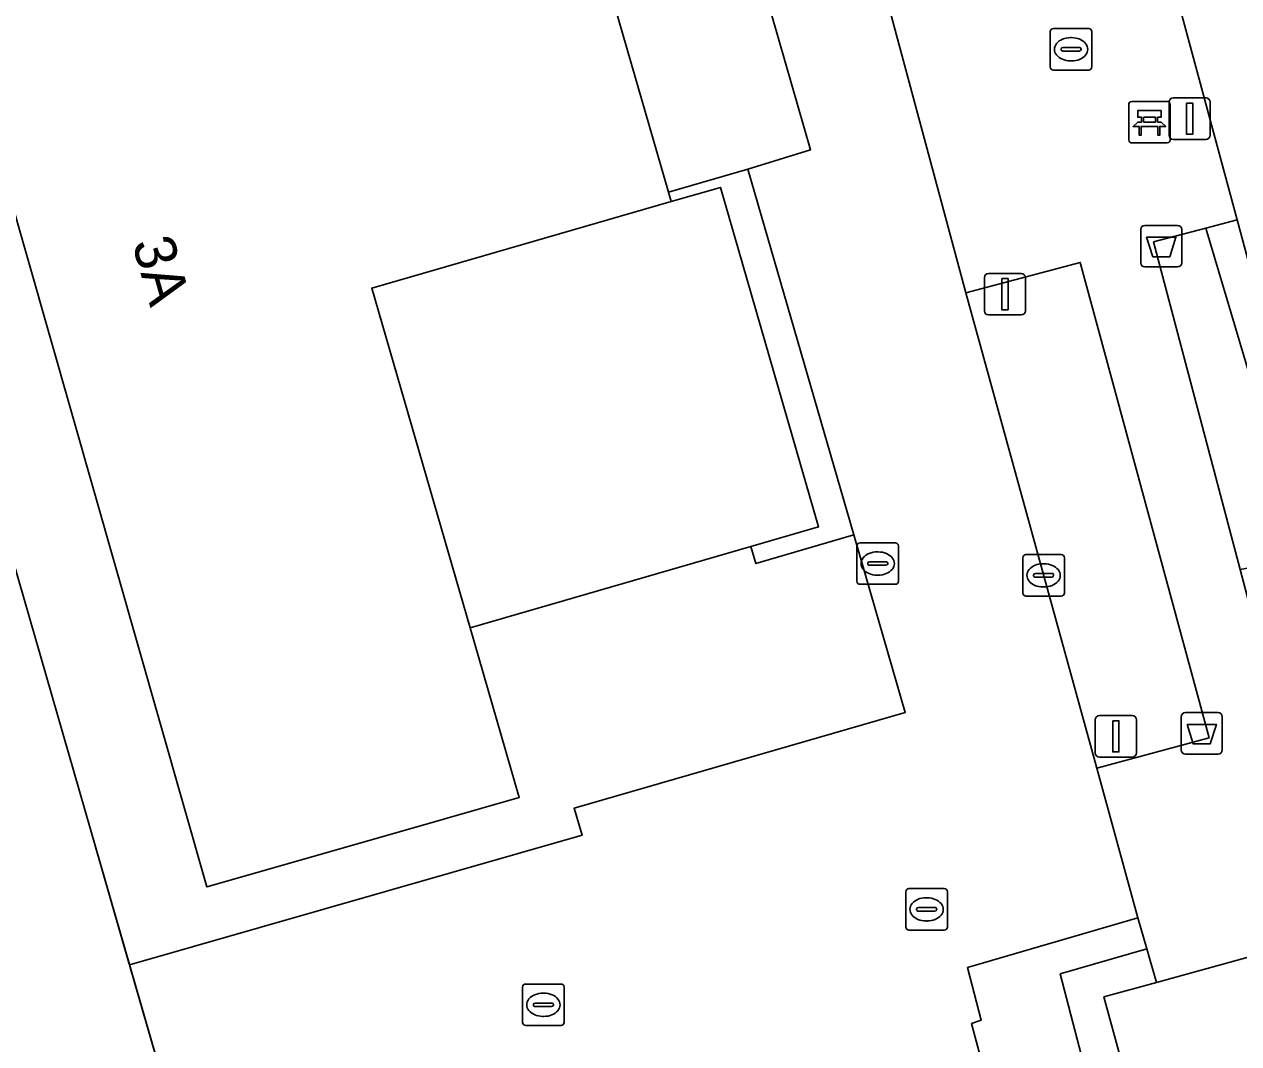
# Model space of a CAD drawing. Extents: x 159053 to 160042, y 380449 to 381423.
# Drawn here: x 159355.9 to 159385.17, y 380559.07 to 380583.63 of the extents above; entities that cross this region are included whole.
import ezdxf

# ---------------------------------------------------------------- set-up
doc = ezdxf.new("R2010")
doc.units = 0
for name, color, linetype in [('IMGEO_Afvalbak', 7, 'Continuous'), ('IMGEO_Bank', 7, 'Continuous'), ('IMGEO_Brandkraan', 7, 'Continuous'), ('IMGEO_Groenvoorziening', 7, 'Continuous'), ('IMGEO_Haag', 7, 'Continuous'), ('IMGEO_Hek', 7, 'Continuous'), ('IMGEO_Kolk', 7, 'Continuous'), ('IMGEO_Lichtmast', 7, 'Continuous'), ('IMGEO_Pand', 7, 'Continuous'), ('IMGEO_Pand_nummerreeks', 7, 'Continuous'), ('IMGEO_Rioolput', 7, 'Continuous'), ('IMGEO_Terreindeel_gesloten', 7, 'Continuous'), ('IMGEO_Terreindeel_halfverhard', 7, 'Continuous'), ('IMGEO_Voetpad_open', 7, 'Continuous')]:
    doc.layers.add(name, color=color, linetype=linetype)

msp = doc.modelspace()

# ---------------------------------------------------------------- linework, layer by layer
at = {"layer": 'IMGEO_Afvalbak'}
for p, q in [((159382.904, 380578.789), (159383.694, 380578.789)), ((159383.694, 380578.789), (159382.904, 380578.789)), ((159382.804, 380577.889), (159382.804, 380578.689)), ((159382.804, 380578.689), (159382.804, 380577.889)), ((159383.794, 380578.689), (159383.794, 380577.889)), ((159383.794, 380577.889), (159383.794, 380578.689)), ((159383.694, 380577.789), (159382.904, 380577.789)), ((159382.904, 380577.789), (159383.694, 380577.789)), ((159383.779, 380566.15), (159383.779, 380566.95)), ((159383.779, 380566.95), (159383.779, 380566.15)), ((159383.879, 380567.05), (159384.669, 380567.05)), ((159384.669, 380567.05), (159383.879, 380567.05)), ((159384.769, 380566.95), (159384.769, 380566.15)), ((159384.769, 380566.15), (159384.769, 380566.95)), ((159384.669, 380566.05), (159383.879, 380566.05)), ((159383.879, 380566.05), (159384.669, 380566.05))]:
    msp.add_line(p, q, dxfattribs=at)
for points in [[(159382.947, 380578.503), (159383.651, 380578.503), (159383.502, 380578.033), (159383.096, 380578.033), (159382.947, 380578.503)], [(159383.922, 380566.764), (159384.626, 380566.764), (159384.477, 380566.294), (159384.071, 380566.294), (159383.922, 380566.764)]]:
    msp.add_lwpolyline(points, dxfattribs=at)
for centre, start, end in [((159382.904, 380578.689), 90, 180), ((159382.904, 380578.689), 90, 180), ((159383.694, 380578.689), 0, 90), ((159383.694, 380578.689), 360, 90), ((159382.904, 380577.889), 180, 270), ((159382.904, 380577.889), 180, 270), ((159383.694, 380577.889), 270, 0), ((159383.694, 380577.889), 270, 0), ((159383.879, 380566.95), 90, 180), ((159383.879, 380566.95), 90, 180), ((159384.669, 380566.95), 0, 90), ((159384.669, 380566.95), 360, 90), ((159383.879, 380566.15), 180, 270), ((159383.879, 380566.15), 180, 270), ((159384.669, 380566.15), 270, 0), ((159384.669, 380566.15), 270, 0)]:
    msp.add_arc(centre, 0.1, start, end, dxfattribs=at)
at = {"layer": 'IMGEO_Bank'}
for p, q in [((159382.591, 380581.778), (159383.432, 380581.778)), ((159383.432, 380581.778), (159382.591, 380581.778)), ((159383.516, 380581.703), (159383.516, 380580.862)), ((159383.516, 380580.862), (159383.516, 380581.703)), ((159382.516, 380580.853), (159382.516, 380581.694)), ((159382.516, 380581.694), (159382.516, 380580.853)), ((159383.213, 380581.176), (159382.82, 380581.176)), ((159382.825, 380581.284), (159382.825, 380581.39)), ((159382.869, 380581.39), (159382.869, 380581.284)), ((159383.157, 380581.396), (159382.875, 380581.396)), ((159382.875, 380581.278), (159383.157, 380581.278)), ((159383.163, 380581.284), (159383.163, 380581.39)), ((159383.207, 380581.39), (159383.207, 380581.284)), ((159383.441, 380580.778), (159382.6, 380580.778)), ((159382.6, 380580.778), (159383.441, 380580.778))]:
    msp.add_line(p, q, dxfattribs=at)
for points in [[(159382.819, 380581.396), (159382.733, 380581.396), (159382.733, 380581.557), (159383.296, 380581.557), (159383.296, 380581.396), (159383.213, 380581.396)], [(159382.763, 380581.176), (159382.621, 380581.176), (159382.733, 380581.278), (159382.819, 380581.278)], [(159382.813, 380581.169), (159382.813, 380580.962), (159382.77, 380580.962), (159382.77, 380581.169)], [(159383.213, 380581.278), (159383.296, 380581.278), (159383.408, 380581.176), (159383.269, 380581.176)], [(159383.263, 380581.169), (159383.263, 380580.962), (159383.219, 380580.962), (159383.219, 380581.169)]]:
    msp.add_lwpolyline(points, dxfattribs=at)
for centre, radius, start, end in [((159382.594, 380581.7), 0.0779, 92.4484, 184.2845), ((159382.594, 380581.7), 0.0779, 92.4484, 184.2845), ((159383.438, 380581.7), 0.0779, 2.4484, 94.2845), ((159383.438, 380581.7), 0.0779, 2.4484, 94.2845), ((159382.763, 380581.169), 0.00671, 2.8957, 87.1043), ((159382.82, 380581.169), 0.00671, 92.8957, 177.1043), ((159382.818, 380581.389), 0.00671, 2.8957, 87.1043), ((159382.818, 380581.285), 0.00671, 272.8957, 357.1043), ((159382.875, 380581.389), 0.00671, 92.8957, 177.1043), ((159382.875, 380581.285), 0.00671, 182.8957, 267.1043), ((159383.157, 380581.389), 0.00671, 2.8957, 87.1043), ((159383.157, 380581.285), 0.00671, 272.8957, 357.1043), ((159383.214, 380581.389), 0.00671, 92.8957, 177.1043), ((159383.214, 380581.285), 0.00671, 182.8957, 267.1043), ((159383.212, 380581.169), 0.00671, 2.8957, 87.1043), ((159383.269, 380581.169), 0.00671, 92.8957, 177.1043), ((159382.594, 380580.856), 0.0779, 182.4484, 274.2845), ((159382.594, 380580.856), 0.0779, 182.4484, 274.2845), ((159383.438, 380580.856), 0.0779, 272.4484, 4.2845), ((159383.438, 380580.856), 0.0779, 272.4484, 4.2845)]:
    msp.add_arc(centre, radius, start, end, dxfattribs=at)
at = {"layer": 'IMGEO_Brandkraan'}
for p, q in [((159375.966, 380570.216), (159375.966, 380571.068)), ((159376.041, 380571.142), (159376.893, 380571.142)), ((159376.454, 380570.922), (159376.479, 380570.922)), ((159376.967, 380571.068), (159376.967, 380570.216)), ((159376.225, 380570.636), (159376.225, 380570.648)), ((159376.663, 380570.599), (159376.265, 380570.599)), ((159376.268, 380570.685), (159376.666, 380570.685)), ((159376.709, 380570.648), (159376.709, 380570.636)), ((159376.477, 380570.362), (159376.452, 380570.362)), ((159376.893, 380570.142), (159376.041, 380570.142))]:
    msp.add_line(p, q, dxfattribs=at)
for points in [[(159375.966, 380570.216), (159375.966, 380571.068)], [(159376.041, 380571.142), (159376.893, 380571.142)], [(159376.967, 380571.068), (159376.967, 380570.216)], [(159376.893, 380570.142), (159376.041, 380570.142)]]:
    msp.add_lwpolyline(points, dxfattribs=at)
for centre, radius, start, end in [((159376.043, 380571.066), 0.0765, 91.552, 178.448), ((159376.043, 380571.066), 0.0765, 91.552, 178.448), ((159376.891, 380571.066), 0.0765, 1.552, 88.448), ((159376.891, 380571.066), 0.0765, 1.552, 88.448), ((159376.265, 380570.645), 0.0403, 85.8775, 175.7526), ((159376.262, 380570.635), 0.0366, 178.938, 274.7102), ((159376.666, 380570.642), 0.043, 264.8664, 352.4533), ((159376.67, 380570.647), 0.0386, 1.7309, 96.639), ((159376.043, 380570.218), 0.0765, 181.552, 268.448), ((159376.043, 380570.218), 0.0765, 181.552, 268.448), ((159376.891, 380570.218), 0.0765, 271.552, 358.448), ((159376.891, 380570.218), 0.0765, 271.552, 358.448)]:
    msp.add_arc(centre, radius, start, end, dxfattribs=at)
for centre, major_axis, ratio, start_param, end_param in [((159376.453, 380570.642), (-0.387, 0.002), 0.722429, 4.712389, 7.853982), ((159376.478, 380570.642), (-0.39, 0.002), 0.717154, 1.570796, 4.712389)]:
    msp.add_ellipse(centre, major_axis=major_axis, ratio=ratio, start_param=start_param, end_param=end_param, dxfattribs=at)
at = {"layer": 'IMGEO_Groenvoorziening'}
for points in [[(159357.369, 380564.683), (159349.331, 380592.56), (159346.947, 380600.826), (159346.774, 380601.426), (159338.841, 380599.209), (159338.36, 380599.075), (159339.254, 380595.623), (159344.292, 380576.221), (159349.404, 380556.748), (159351.079, 380550.293), (159360.774, 380552.877), (159358.448, 380560.94), (159358.439, 380560.973), (159358.424, 380561.023)], [(159422.093, 380552.135), (159386.743, 380542.548), (159381.917, 380560.199), (159383.181, 380560.548), (159382.949, 380561.361), (159380.865, 380560.752), (159385.994, 380541.036), (159423.423, 380551.328), (159421.053, 380559.766), (159454.836, 380569.06), (159456.103, 380570.642), (159451.468, 380587.596), (159461.029, 380590.266), (159460.552, 380592.05), (159460.061, 380591.918), (159460.426, 380590.563), (159450.507, 380587.804), (159455.23, 380570.048), (159419.835, 380560.5)], [(159385.129, 380578.922), (159384.374, 380578.723), (159386.292, 380572.275), (159386.633, 380571.661), (159387.086, 380571.784), (159386.902, 380572.418), (159386.729, 380572.996)], [(159386.633, 380571.661), (159386.292, 380572.275), (159384.374, 380578.723), (159383.114, 380578.39), (159385.201, 380570.495), (159386.808, 380570.803)], [(159384.456, 380566.438), (159381.347, 380577.898), (159378.59, 380577.165), (159381.743, 380565.708)]]:
    msp.add_lwpolyline(points, close=True, dxfattribs=at)
msp.add_lwpolyline([(159478.465, 380596.984), (159460.973, 380592.164), (159460.552, 380592.05), (159461.029, 380590.266), (159451.468, 380587.596), (159456.103, 380570.642), (159454.836, 380569.06), (159421.053, 380559.766), (159423.423, 380551.328), (159385.994, 380541.036), (159380.865, 380560.752), (159382.949, 380561.361), (159382.736, 380562.106), (159378.627, 380560.909), (159378.96, 380559.642), (159378.727, 380559.561), (159384.113, 380539.402), (159366.014, 380534.705), (159367.048, 380531.119), (159403.642, 380540.747), (159438.635, 380550.23), (159479.833, 380596.64)], dxfattribs=at)
at = {"layer": 'IMGEO_Haag'}
msp.add_lwpolyline([(159422.093, 380552.135), (159386.743, 380542.548), (159381.917, 380560.199), (159383.181, 380560.548), (159382.949, 380561.361), (159380.865, 380560.752), (159385.994, 380541.036), (159423.423, 380551.328), (159421.053, 380559.766), (159454.836, 380569.06), (159456.103, 380570.642), (159451.468, 380587.596), (159461.029, 380590.266), (159460.552, 380592.05), (159460.061, 380591.918), (159460.426, 380590.563), (159450.507, 380587.804), (159455.23, 380570.048), (159419.835, 380560.5)], close=True, dxfattribs=at)
at = {"layer": 'IMGEO_Hek'}
for points in [[(159378.936, 380601.858), (159385.129, 380578.922)], [(159357.369, 380564.683), (159349.331, 380592.56)], [(159385.129, 380578.922), (159386.729, 380572.996), (159386.902, 380572.418), (159413.391, 380579.576), (159420.037, 380581.372), (159419.844, 380582.068)], [(159366.014, 380534.705), (159360.774, 380552.877), (159357.369, 380564.683)], [(159389.787, 380562.37), (159383.181, 380560.548)], [(159383.181, 380560.548), (159381.917, 380560.199), (159386.743, 380542.548), (159422.093, 380552.135), (159419.835, 380560.5)]]:
    msp.add_lwpolyline(points, dxfattribs=at)
at = {"layer": 'IMGEO_Kolk'}
for p, q in [((159380.625, 380582.607), (159380.625, 380583.459)), ((159380.7, 380583.533), (159381.552, 380583.533)), ((159381.626, 380583.459), (159381.626, 380582.607)), ((159381.113, 380583.313), (159381.138, 380583.313)), ((159380.884, 380583.027), (159380.884, 380583.039)), ((159381.322, 380582.99), (159380.924, 380582.99)), ((159380.927, 380583.076), (159381.325, 380583.076)), ((159381.368, 380583.039), (159381.368, 380583.027)), ((159381.136, 380582.753), (159381.111, 380582.753)), ((159381.552, 380582.533), (159380.7, 380582.533)), ((159379.963, 380569.93), (159379.963, 380570.782)), ((159380.038, 380570.856), (159380.89, 380570.856)), ((159380.451, 380570.636), (159380.476, 380570.636)), ((159380.964, 380570.782), (159380.964, 380569.93)), ((159380.222, 380570.35), (159380.222, 380570.362)), ((159380.66, 380570.313), (159380.262, 380570.313)), ((159380.265, 380570.399), (159380.663, 380570.399)), ((159380.706, 380570.362), (159380.706, 380570.35)), ((159380.474, 380570.076), (159380.449, 380570.076)), ((159380.89, 380569.856), (159380.038, 380569.856)), ((159367.91, 380559.583), (159367.91, 380560.435)), ((159367.985, 380560.509), (159368.837, 380560.509)), ((159368.911, 380560.435), (159368.911, 380559.583)), ((159368.212, 380560.052), (159368.61, 380560.052)), ((159368.398, 380560.289), (159368.423, 380560.289)), ((159368.169, 380560.003), (159368.169, 380560.015)), ((159368.607, 380559.966), (159368.209, 380559.966)), ((159368.653, 380560.015), (159368.653, 380560.003)), ((159368.837, 380559.509), (159367.985, 380559.509)), ((159368.421, 380559.729), (159368.396, 380559.729))]:
    msp.add_line(p, q, dxfattribs=at)
for points in [[(159380.625, 380582.607), (159380.625, 380583.459)], [(159380.7, 380583.533), (159381.552, 380583.533)], [(159381.626, 380583.459), (159381.626, 380582.607)], [(159381.552, 380582.533), (159380.7, 380582.533)], [(159379.963, 380569.93), (159379.963, 380570.782)], [(159380.038, 380570.856), (159380.89, 380570.856)], [(159380.964, 380570.782), (159380.964, 380569.93)], [(159380.89, 380569.856), (159380.038, 380569.856)], [(159367.91, 380559.583), (159367.91, 380560.435)], [(159367.985, 380560.509), (159368.837, 380560.509)], [(159368.911, 380560.435), (159368.911, 380559.583)], [(159368.837, 380559.509), (159367.985, 380559.509)]]:
    msp.add_lwpolyline(points, dxfattribs=at)
for centre, radius, start, end in [((159380.702, 380583.457), 0.0765, 91.552, 178.448), ((159380.702, 380583.457), 0.0765, 91.552, 178.448), ((159381.55, 380583.457), 0.0765, 1.552, 88.448), ((159381.55, 380583.457), 0.0765, 1.552, 88.448), ((159380.924, 380583.036), 0.0403, 85.8775, 175.7526), ((159380.921, 380583.026), 0.0366, 178.938, 274.7102), ((159381.325, 380583.033), 0.043, 264.8664, 352.4533), ((159381.329, 380583.038), 0.0386, 1.7309, 96.639), ((159380.702, 380582.609), 0.0765, 181.552, 268.448), ((159380.702, 380582.609), 0.0765, 181.552, 268.448), ((159381.55, 380582.609), 0.0765, 271.552, 358.448), ((159381.55, 380582.609), 0.0765, 271.552, 358.448), ((159380.04, 380570.78), 0.0765, 91.552, 178.448), ((159380.04, 380570.78), 0.0765, 91.552, 178.448), ((159380.888, 380570.78), 0.0765, 1.552, 88.448), ((159380.888, 380570.78), 0.0765, 1.552, 88.448), ((159380.262, 380570.359), 0.0403, 85.8775, 175.7526), ((159380.259, 380570.349), 0.0366, 178.938, 274.7102), ((159380.663, 380570.356), 0.043, 264.8664, 352.4533), ((159380.667, 380570.361), 0.0386, 1.7309, 96.639), ((159380.04, 380569.932), 0.0765, 181.552, 268.448), ((159380.04, 380569.932), 0.0765, 181.552, 268.448), ((159380.888, 380569.932), 0.0765, 271.552, 358.448), ((159380.888, 380569.932), 0.0765, 271.552, 358.448), ((159367.987, 380560.433), 0.0765, 91.552, 178.448), ((159367.987, 380560.433), 0.0765, 91.552, 178.448), ((159368.835, 380560.433), 0.0765, 1.552, 88.448), ((159368.835, 380560.433), 0.0765, 1.552, 88.448), ((159368.209, 380560.012), 0.0403, 85.8775, 175.7526), ((159368.614, 380560.014), 0.0386, 1.7309, 96.639), ((159368.206, 380560.002), 0.0366, 178.938, 274.7102), ((159368.61, 380560.009), 0.043, 264.8664, 352.4533), ((159367.987, 380559.585), 0.0765, 181.552, 268.448), ((159367.987, 380559.585), 0.0765, 181.552, 268.448), ((159368.835, 380559.585), 0.0765, 271.552, 358.448), ((159368.835, 380559.585), 0.0765, 271.552, 358.448)]:
    msp.add_arc(centre, radius, start, end, dxfattribs=at)
for centre, major_axis, ratio, start_param, end_param in [((159381.112, 380583.033), (-0.387, 0.002), 0.722429, 4.712389, 7.853982), ((159381.137, 380583.033), (-0.39, 0.002), 0.717154, 1.570796, 4.712389), ((159380.45, 380570.356), (-0.387, 0.002), 0.722429, 4.712389, 7.853982), ((159380.475, 380570.356), (-0.39, 0.002), 0.717154, 1.570796, 4.712389), ((159368.397, 380560.009), (-0.387, 0.002), 0.722429, 4.712389, 7.853982), ((159368.422, 380560.009), (-0.39, 0.002), 0.717154, 1.570796, 4.712389)]:
    msp.add_ellipse(centre, major_axis=major_axis, ratio=ratio, start_param=start_param, end_param=end_param, dxfattribs=at)
at = {"layer": 'IMGEO_Lichtmast'}
for p, q in [((159383.487, 380580.962), (159383.487, 380581.762)), ((159383.487, 380581.762), (159383.487, 380580.962)), ((159383.587, 380581.862), (159384.377, 380581.862)), ((159384.377, 380581.862), (159383.587, 380581.862)), ((159384.477, 380581.762), (159384.477, 380580.962)), ((159384.477, 380580.962), (159384.477, 380581.762)), ((159384.377, 380580.862), (159383.587, 380580.862)), ((159383.587, 380580.862), (159384.377, 380580.862)), ((159379.136, 380577.631), (159379.926, 380577.631)), ((159379.926, 380577.631), (159379.136, 380577.631)), ((159379.036, 380576.731), (159379.036, 380577.531)), ((159379.036, 380577.531), (159379.036, 380576.731)), ((159380.026, 380577.531), (159380.026, 380576.731)), ((159380.026, 380576.731), (159380.026, 380577.531)), ((159379.926, 380576.631), (159379.136, 380576.631)), ((159379.136, 380576.631), (159379.926, 380576.631)), ((159381.71, 380566.078), (159381.71, 380566.878)), ((159381.71, 380566.878), (159381.71, 380566.078)), ((159381.81, 380566.978), (159382.6, 380566.978)), ((159382.6, 380566.978), (159381.81, 380566.978)), ((159382.7, 380566.878), (159382.7, 380566.078)), ((159382.7, 380566.078), (159382.7, 380566.878)), ((159382.6, 380565.978), (159381.81, 380565.978)), ((159381.81, 380565.978), (159382.6, 380565.978))]:
    msp.add_line(p, q, dxfattribs=at)
for points in [[(159383.907, 380581.737), (159384.057, 380581.737), (159384.057, 380580.987), (159383.907, 380580.987), (159383.907, 380581.737)], [(159379.456, 380577.506), (159379.606, 380577.506), (159379.606, 380576.756), (159379.456, 380576.756), (159379.456, 380577.506)], [(159382.13, 380566.853), (159382.28, 380566.853), (159382.28, 380566.103), (159382.13, 380566.103), (159382.13, 380566.853)]]:
    msp.add_lwpolyline(points, dxfattribs=at)
for centre, start, end in [((159383.587, 380581.762), 90, 180), ((159383.587, 380581.762), 90, 180), ((159384.377, 380581.762), 0, 90), ((159384.377, 380581.762), 360, 90), ((159383.587, 380580.962), 180, 270), ((159383.587, 380580.962), 180, 270), ((159384.377, 380580.962), 270, 0), ((159384.377, 380580.962), 270, 0), ((159379.136, 380577.531), 90, 180), ((159379.136, 380577.531), 90, 180), ((159379.926, 380577.531), 0, 90), ((159379.926, 380577.531), 360, 90), ((159379.136, 380576.731), 180, 270), ((159379.136, 380576.731), 180, 270), ((159379.926, 380576.731), 270, 0), ((159379.926, 380576.731), 270, 0), ((159381.81, 380566.878), 90, 180), ((159381.81, 380566.878), 90, 180), ((159382.6, 380566.878), 0, 90), ((159382.6, 380566.878), 360, 90), ((159381.81, 380566.078), 180, 270), ((159381.81, 380566.078), 180, 270), ((159382.6, 380566.078), 270, 0), ((159382.6, 380566.078), 270, 0)]:
    msp.add_arc(centre, 0.1, start, end, dxfattribs=at)
at = {"layer": 'IMGEO_Pand'}
msp.add_lwpolyline([(159366.079, 380594.878), (159362.454, 380593.844), (159361.878, 380595.864), (159359.474, 380595.178), (159360.05, 380593.158), (159352.285, 380590.943), (159359.174, 380566.798), (159360.3, 380562.854), (159365.109, 380564.227), (159367.83, 380565.003), (159366.645, 380569.096), (159364.276, 380577.279), (159371.491, 380579.362), (159371.423, 380579.593), (159368.96, 380588.123), (159368.078, 380587.872)], close=True, dxfattribs=at)
at = {"layer": 'IMGEO_Rioolput'}
for p, q in [((159377.144, 380561.882), (159377.144, 380562.734)), ((159377.219, 380562.808), (159378.071, 380562.808)), ((159378.145, 380562.734), (159378.145, 380561.882)), ((159377.632, 380562.588), (159377.657, 380562.588)), ((159377.403, 380562.302), (159377.403, 380562.314)), ((159377.841, 380562.265), (159377.443, 380562.265)), ((159377.446, 380562.351), (159377.844, 380562.351)), ((159377.887, 380562.314), (159377.887, 380562.302)), ((159378.071, 380561.808), (159377.219, 380561.808)), ((159377.655, 380562.028), (159377.63, 380562.028))]:
    msp.add_line(p, q, dxfattribs=at)
for points in [[(159377.144, 380561.882), (159377.144, 380562.734)], [(159377.219, 380562.808), (159378.071, 380562.808)], [(159378.145, 380562.734), (159378.145, 380561.882)], [(159378.071, 380561.808), (159377.219, 380561.808)]]:
    msp.add_lwpolyline(points, dxfattribs=at)
for centre, radius, start, end in [((159377.221, 380562.732), 0.0765, 91.552, 178.448), ((159377.221, 380562.732), 0.0765, 91.552, 178.448), ((159378.069, 380562.732), 0.0765, 1.552, 88.448), ((159378.069, 380562.732), 0.0765, 1.552, 88.448), ((159377.443, 380562.311), 0.0403, 85.8775, 175.7526), ((159377.44, 380562.301), 0.0366, 178.938, 274.7102), ((159377.844, 380562.308), 0.043, 264.8664, 352.4533), ((159377.848, 380562.313), 0.0386, 1.7309, 96.639), ((159377.221, 380561.884), 0.0765, 181.552, 268.448), ((159377.221, 380561.884), 0.0765, 181.552, 268.448), ((159378.069, 380561.884), 0.0765, 271.552, 358.448), ((159378.069, 380561.884), 0.0765, 271.552, 358.448)]:
    msp.add_arc(centre, radius, start, end, dxfattribs=at)
for centre, major_axis, ratio, start_param, end_param in [((159377.631, 380562.308), (-0.387, 0.002), 0.722429, 4.712389, 7.853982), ((159377.656, 380562.308), (-0.39, 0.002), 0.717154, 1.570796, 4.712389)]:
    msp.add_ellipse(centre, major_axis=major_axis, ratio=ratio, start_param=start_param, end_param=end_param, dxfattribs=at)
at = {"layer": 'IMGEO_Terreindeel_gesloten'}
msp.add_lwpolyline([(159419.835, 380560.5), (159417.331, 380569.97), (159409.569, 380567.829), (159389.787, 380562.37), (159383.181, 380560.548), (159381.917, 380560.199), (159386.743, 380542.548), (159422.093, 380552.135)], close=True, dxfattribs=at)
at = {"layer": 'IMGEO_Terreindeel_halfverhard'}
msp.add_lwpolyline([(159411.978, 380611.14), (159410.439, 380616.826), (159377.318, 380607.849), (159377.482, 380607.241), (159378.936, 380601.858), (159385.129, 380578.922), (159386.729, 380572.996), (159386.902, 380572.418), (159413.415, 380579.583), (159420.037, 380581.372), (159419.844, 380582.068), (159418.261, 380587.917)], close=True, dxfattribs=at)
at = {"layer": 'IMGEO_Voetpad_open'}
for points in [[(159378.727, 380559.561), (159378.96, 380559.642), (159378.627, 380560.909), (159382.736, 380562.106), (159381.743, 380565.708), (159378.59, 380577.165), (159372.458, 380599.947), (159370.43, 380607.703), (159370.122, 380608.884), (159369.608, 380608.744), (159368.494, 380612.849), (159351.357, 380608.203), (159350.078, 380607.857), (159348.899, 380607.537), (159349.047, 380607.148), (159347.263, 380606.676), (159345.349, 380606.17), (159346.774, 380601.426), (159346.947, 380600.826), (159349.47, 380601.52), (159364.058, 380605.534)], [(159373.131, 380608.456), (159375.231, 380600.697), (159372.458, 380599.947), (159378.59, 380577.165), (159381.347, 380577.898), (159384.456, 380566.438), (159381.743, 380565.708), (159382.736, 380562.106), (159382.949, 380561.361), (159383.181, 380560.548), (159389.787, 380562.37), (159409.569, 380567.829), (159417.331, 380569.97), (159416.517, 380573.072), (159415.161, 380578.241), (159450.507, 380587.804), (159460.426, 380590.563), (159460.061, 380591.918), (159458.856, 380591.727), (159425.519, 380582.771), (159425.367, 380583.331), (159423.745, 380589.306), (159417.429, 380612.57)], [(159411.978, 380611.14), (159418.261, 380587.917), (159419.844, 380582.068), (159420.037, 380581.372), (159413.415, 380579.583), (159414.705, 380574.74), (159386.151, 380566.901), (159385.201, 380570.495), (159383.114, 380578.39), (159384.374, 380578.723), (159385.129, 380578.922), (159378.936, 380601.858), (159378.191, 380601.66), (159376.974, 380601.336), (159375.567, 380606.708), (159375.484, 380607.024), (159374.673, 380610.12)], [(159364.058, 380605.534), (159349.47, 380601.52), (159346.947, 380600.826), (159349.331, 380592.56), (159357.369, 380564.683), (159358.424, 380561.023), (159358.439, 380560.973), (159369.343, 380564.094), (159369.154, 380564.747), (159377.128, 380567.056), (159376.291, 380569.946)], [(159366.712, 380604.359), (159366.995, 380603.315), (159368.482, 380597.841), (159369.159, 380595.348), (159368.873, 380595.27), (159370.801, 380588.679), (159372.405, 380589.101), (159374.85, 380580.61), (159373.337, 380580.146), (159375.89, 380571.329), (159376.291, 380569.946), (159377.128, 380567.056), (159369.154, 380564.747), (159369.343, 380564.094), (159358.439, 380560.973), (159358.448, 380560.94), (159360.774, 380552.877), (159366.014, 380534.705), (159384.113, 380539.402), (159378.727, 380559.561)], [(159376.291, 380569.946), (159375.89, 380571.329), (159373.528, 380570.645), (159373.409, 380571.054), (159366.645, 380569.096), (159367.83, 380565.003), (159365.109, 380564.227), (159360.3, 380562.854), (159359.174, 380566.798), (159352.285, 380590.943)], [(159368.96, 380588.123), (159371.423, 380579.593), (159373.337, 380580.146), (159374.85, 380580.61), (159372.405, 380589.101)]]:
    msp.add_lwpolyline(points, dxfattribs=at)
for points in [[(159373.528, 380570.645), (159375.89, 380571.329), (159373.337, 380580.146), (159371.423, 380579.593), (159371.491, 380579.362), (159372.675, 380579.704), (159375.042, 380571.527), (159373.409, 380571.054)], [(159373.409, 380571.054), (159375.042, 380571.527), (159372.675, 380579.704), (159371.491, 380579.362), (159364.276, 380577.279), (159366.645, 380569.096)]]:
    msp.add_lwpolyline(points, close=True, dxfattribs=at)

# ---------------------------------------------------------------- texts
at = {"layer": 'IMGEO_Pand_nummerreeks'}
msp.add_text('3A', height=1, rotation=285.9257, dxfattribs=at).set_placement((159358.495, 380578.364))

doc.saveas('drawing.dxf')
